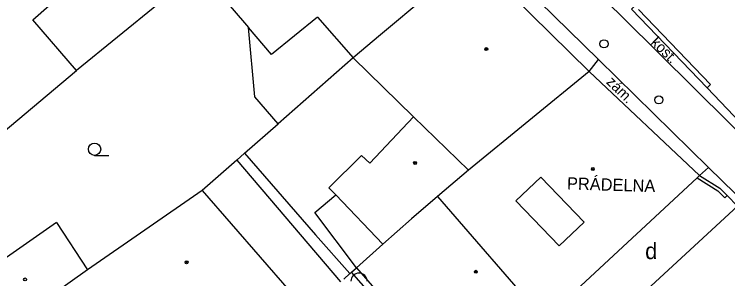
# Model space of a CAD drawing. Extents: x -598233 to -596890, y -1157848 to -1156431.
# Drawn here: x -597364.59 to -597320.92, y -1157417.08 to -1157400.89 of the extents above; entities that cross this region are included whole.
import ezdxf

# ---------------------------------------------------------------- set-up
doc = ezdxf.new("R2010")
doc.units = 0
for name, color, linetype in [('Level 10', 7, 'Continuous'), ('Level 11', 7, 'Continuous'), ('Level 22', 7, 'Continuous'), ('Level 28', 7, 'Continuous'), ('Level 36', 7, 'Continuous'), ('Level 39', 7, 'Continuous'), ('Level 40', 7, 'Continuous'), ('Level 41', 7, 'Continuous'), ('Level 5', 7, 'Continuous'), ('Level 7', 7, 'Continuous'), ('Level 8', 7, 'Continuous')]:
    doc.layers.add(name, color=color, linetype=linetype)

msp = doc.modelspace()

# ---------------------------------------------------------------- linework, layer by layer
at = {"layer": 'Level 10'}
for points in [[(-597341.7, -1157387.02), (-597327.31, -1157401.12), (-597318.67, -1157409.68), (-597315.19, -1157412.87), (-597311.75, -1157416.02), (-597311.44, -1157416.19)], [(-597336.32, -1157396.31), (-597336.09, -1157396.53), (-597328.83, -1157403.6599)], [(-597328.83, -1157403.6599), (-597322.09, -1157410.26)], [(-597322.09, -1157410.26), (-597317.22, -1157415.03), (-597313.64, -1157418.53), (-597313.37, -1157418.8)]]:
    msp.add_lwpolyline(points, dxfattribs=at)
at = {"layer": 'Level 11'}
for points in [[(-597348.44, -1157407.59), (-597349.86, -1157405.94), (-597350.26, -1157401.69)], [(-597343.84, -1157403.55), (-597348.44, -1157407.59)], [(-597329.4, -1157404.39), (-597328.83, -1157403.6599)], [(-597367.1, -1157409.62), (-597360.79, -1157404.34)], [(-597340.15, -1157407.16), (-597342.83, -1157410), (-597343.34, -1157409.54), (-597345.34, -1157411.51), (-597344.91, -1157411.94), (-597342.03, -1157414.97)], [(-597350.5, -1157409.4), (-597348.44, -1157407.59)], [(-597350.9699, -1157409.81), (-597350.5, -1157409.4)], [(-597350.5, -1157409.4), (-597346.15, -1157414.38)], [(-597350.9699, -1157409.81), (-597353.1, -1157411.67)], [(-597350.9699, -1157409.81), (-597344.62, -1157417.26)], [(-597322.64, -1157410.76), (-597322.09, -1157410.26)], [(-597343.65, -1157416.41), (-597346.2, -1157413.03), (-597344.91, -1157411.94)], [(-597346.15, -1157414.38), (-597344.05, -1157416.76)], [(-597343.95, -1157416.67), (-597343.65, -1157416.4099)], [(-597344.43, -1157417.1), (-597344.05, -1157416.76)], [(-597344.05, -1157416.76), (-597343.95, -1157416.67)], [(-597341.14, -1157419.88), (-597343.95, -1157416.67)]]:
    msp.add_lwpolyline(points, dxfattribs=at)
at = {"layer": 'Level 22'}
msp.add_arc((-597343.49, -1157417.23), 0.5, 0, 180, dxfattribs=at)
at = {"layer": 'Level 28'}
for centre in [(-597328.5, -1157402.7), (-597325.14, -1157406.13)]:
    msp.add_circle(centre, 0.25, dxfattribs=at)
at = {"layer": 'Level 36'}
msp.add_line((-597359.68, -1157409.525), (-597358.805, -1157409.525), dxfattribs=at)
msp.add_circle((-597359.6801, -1157409.1499), 0.375, dxfattribs=at)
at = {"layer": 'Level 39'}
for centre, radius in [((-597335.7, -1157403.02), 0.09), ((-597335.7, -1157403.02), 0.0398), ((-597340.06, -1157409.99), 0.09), ((-597340.06, -1157409.99), 0.0398), ((-597329.18, -1157410.36), 0.09), ((-597329.18, -1157410.36), 0.0398), ((-597354.05, -1157416.07), 0.09), ((-597354.05, -1157416.07), 0.0398), ((-597336.34, -1157416.65), 0.09), ((-597336.34, -1157416.65), 0.0398), ((-597363.93, -1157417.12), 0.09)]:
    msp.add_circle(centre, radius, dxfattribs=at)
at = {"layer": 'Level 5'}
for points in [[(-597363.45, -1157401.24), (-597357.96, -1157396.4)], [(-597336.51, -1157397.39), (-597342.18, -1157402.15)], [(-597336.51, -1157397.39), (-597329.4, -1157404.39)], [(-597353.25, -1157398.19), (-597360.79, -1157404.34)], [(-597353.25, -1157398.19), (-597350.26, -1157401.69)], [(-597360.79, -1157404.34), (-597363.45, -1157401.24)], [(-597346.04, -1157401.07), (-597348.85, -1157403.35)], [(-597346.04, -1157401.07), (-597343.84, -1157403.55)], [(-597348.85, -1157403.35), (-597350.26, -1157401.69)], [(-597342.18, -1157402.15), (-597343.84, -1157403.55)], [(-597343.84, -1157403.55), (-597340.15, -1157407.1599)], [(-597329.4, -1157404.39), (-597336.8, -1157410.44)], [(-597329.4, -1157404.39), (-597322.64, -1157410.76)], [(-597340.15, -1157407.1599), (-597336.8, -1157410.44)], [(-597336.8, -1157410.44), (-597338.68, -1157412.05)], [(-597333.89, -1157412.31), (-597332.36, -1157410.85)], [(-597332.36, -1157410.85), (-597329.71, -1157413.61)], [(-597322.79, -1157410.9), (-597330.2, -1157417.77)], [(-597322.64, -1157410.76), (-597322.79, -1157410.9)], [(-597353.1, -1157411.67), (-597360.11, -1157416.54)], [(-597353.1, -1157411.67), (-597347.76, -1157417.79)], [(-597338.68, -1157412.05), (-597340.27, -1157413.4099)], [(-597338.68, -1157412.05), (-597332.17, -1157419.54)], [(-597331.24, -1157415.07), (-597333.89, -1157412.31)], [(-597320.32, -1157412.63), (-597328.27, -1157419.95)], [(-597340.27, -1157413.4099), (-597342.03, -1157414.97), (-597343.65, -1157416.4099)], [(-597362.01, -1157413.63), (-597366.93, -1157417.07)], [(-597362.01, -1157413.63), (-597360.11, -1157416.54)], [(-597329.71, -1157413.61), (-597331.24, -1157415.07)], [(-597360.11, -1157416.54), (-597362.23, -1157418.04)], [(-597343.65, -1157416.4099), (-597340.87, -1157419.59)]]:
    msp.add_lwpolyline(points, dxfattribs=at)
at = {"layer": 'Level 7'}
for points in [[(-597322.19, -1157405.39), (-597326.81, -1157400.58), (-597324.63, -1157398.41)], [(-597321.97, -1157405.18), (-597326.39, -1157400.59)], [(-597321.97, -1157405.18), (-597322.19, -1157405.39)], [(-597322.79, -1157410.9), (-597321.52, -1157411.7), (-597321.09, -1157412.12), (-597320.95, -1157411.98)], [(-597322.64, -1157410.76), (-597321.4, -1157411.54), (-597320.95, -1157411.98)]]:
    msp.add_lwpolyline(points, dxfattribs=at)
at = {"layer": 'Level 8'}
for points in [[(-597322.19, -1157405.39), (-597320.13, -1157407.54)], [(-597320.32, -1157412.63), (-597320.95, -1157411.98)]]:
    msp.add_lwpolyline(points, dxfattribs=at)

# ---------------------------------------------------------------- texts
at = {"layer": 'Level 40'}
for s, rotation, p in [('kost.', 315.56249, (-597325.68, -1157402.67)), ('zám.', 315.55015, (-597328.4, -1157405.08))]:
    msp.add_text(s, height=0.65, rotation=rotation, dxfattribs=at).set_placement(p)
at = {"layer": 'Level 41'}
msp.add_text('PRÁDELNA', height=0.75, rotation=358.2363, dxfattribs=at).set_placement((-597330.77, -1157411.61))
msp.add_text('d', height=1, dxfattribs=at).set_placement((-597325.977, -1157415.875))

doc.saveas('drawing.dxf')
